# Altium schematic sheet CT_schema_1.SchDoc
size 532 x 318 mm
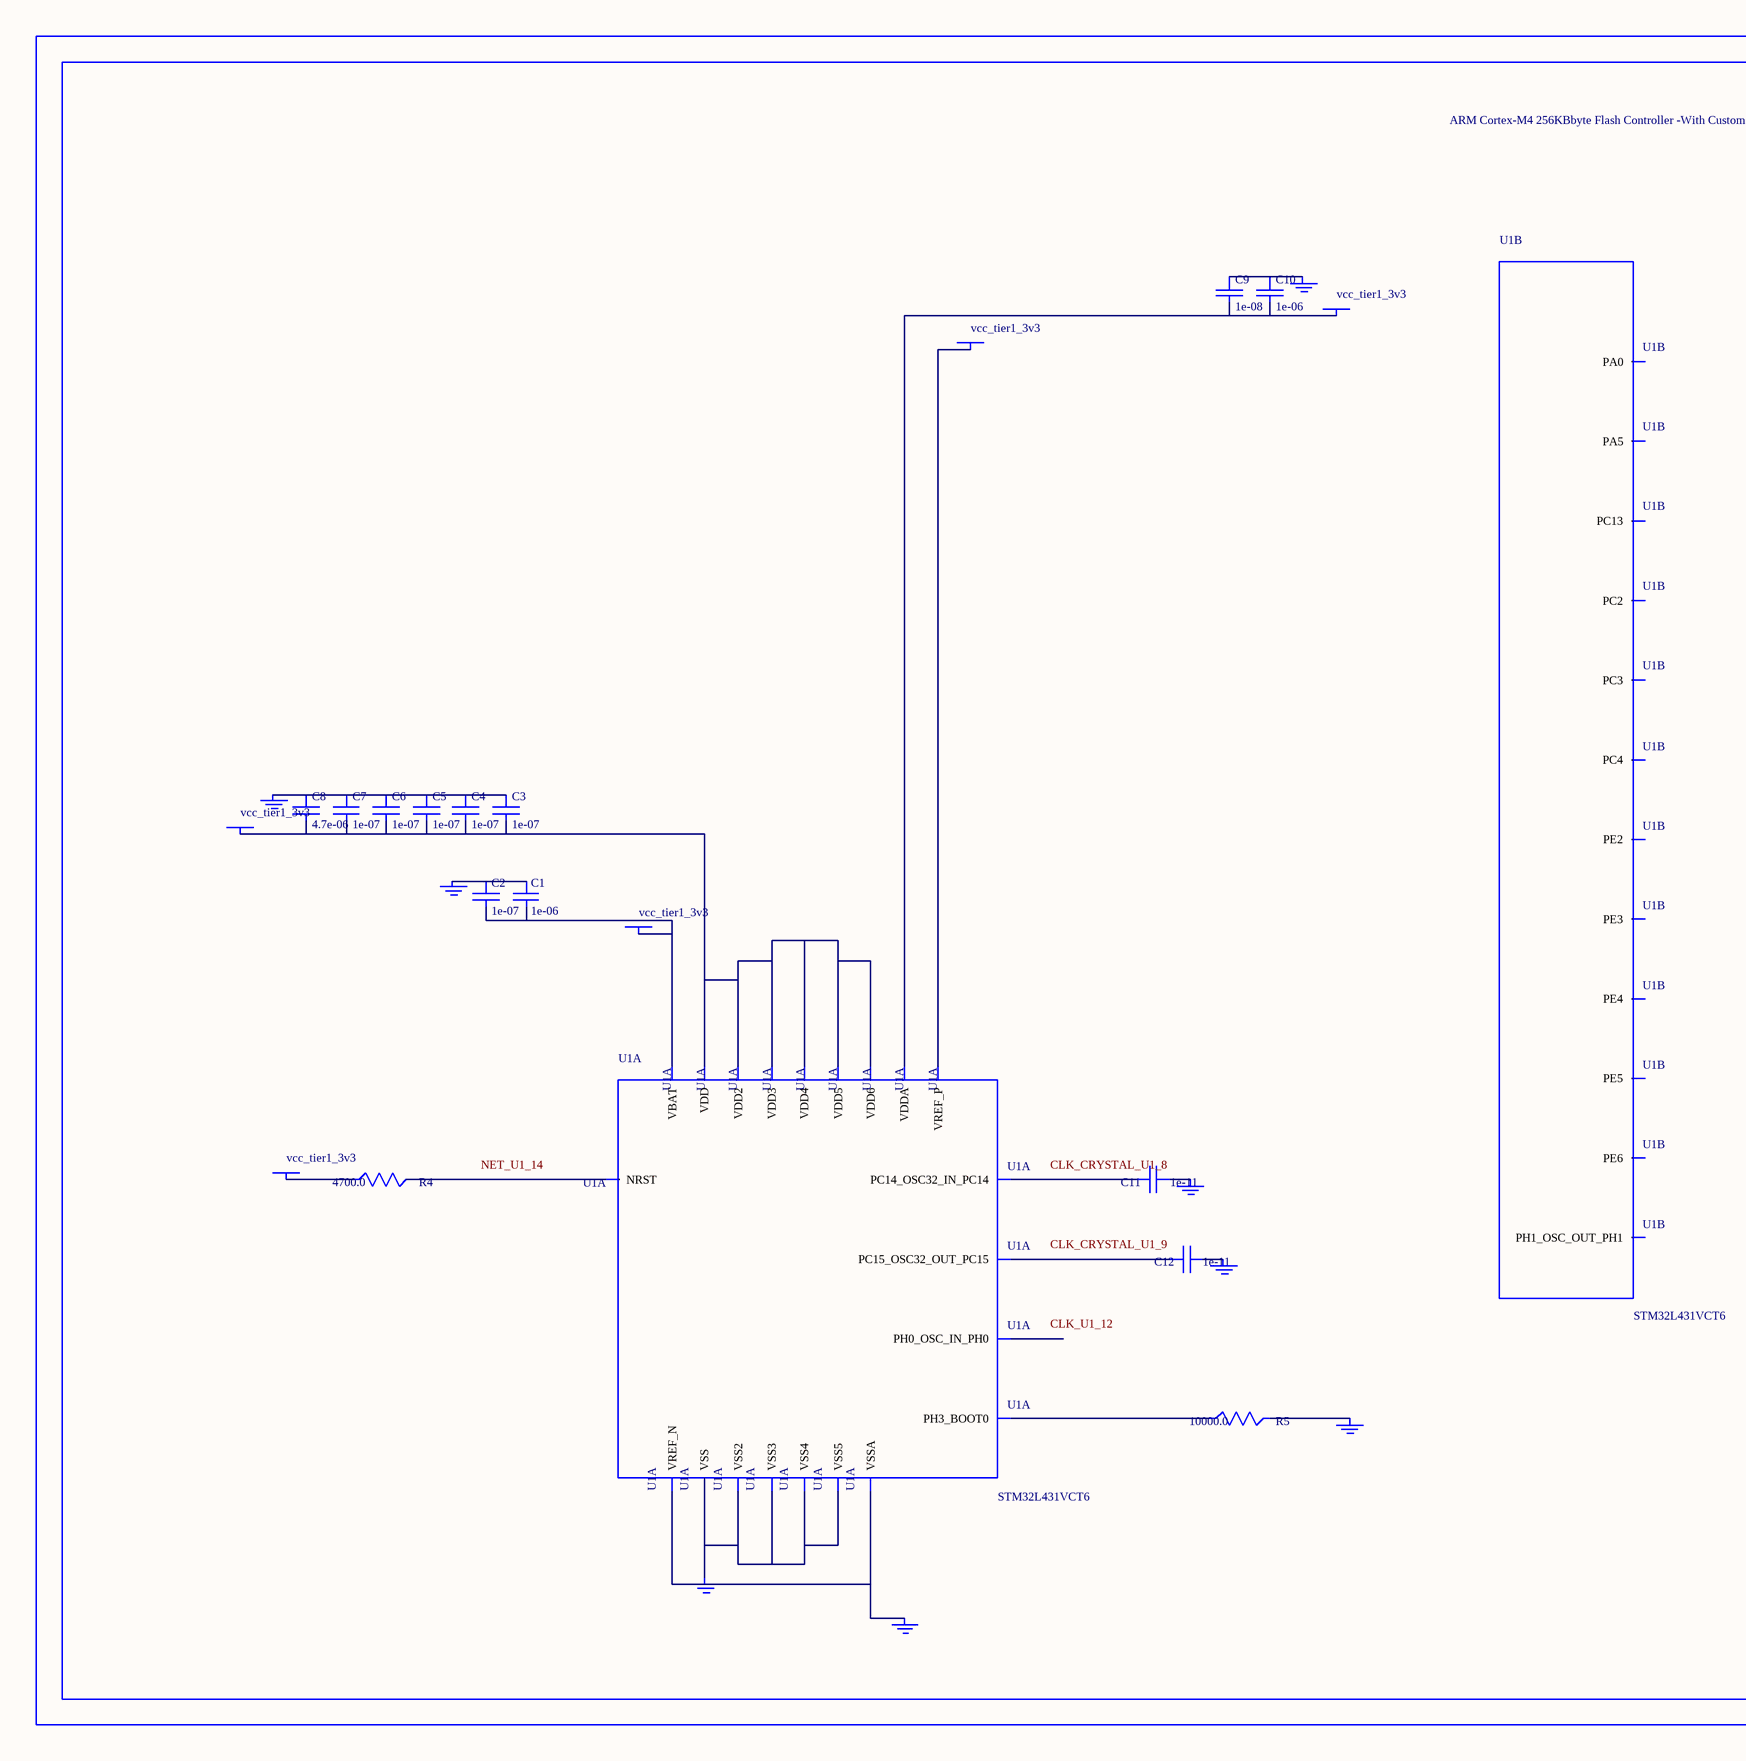
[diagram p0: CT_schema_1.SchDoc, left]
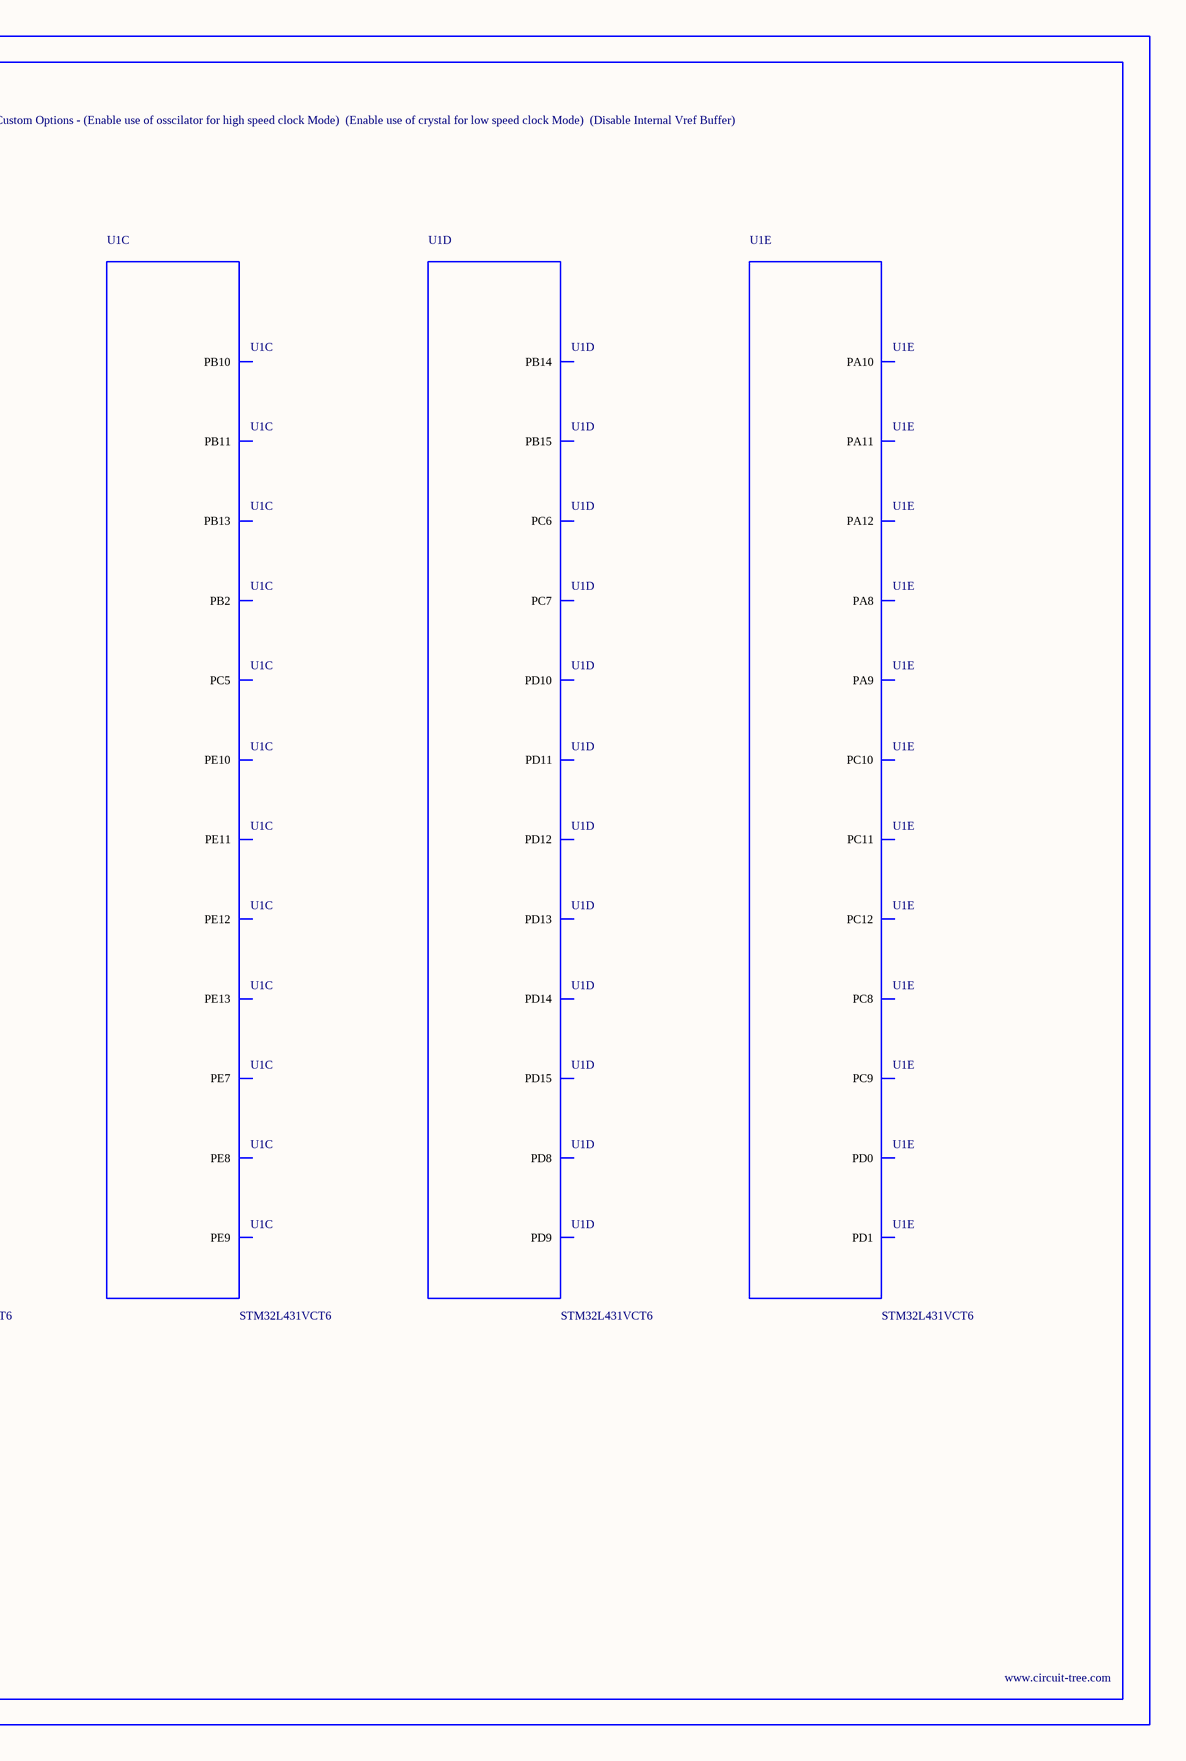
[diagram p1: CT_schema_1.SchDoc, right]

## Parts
BORDER0  (no value)
C1  1e-06  [C0603]
C2  1e-07  [C0603]
C3  1e-07  [C0603]
C4  1e-07  [C0603]
C5  1e-07  [C0603]
C6  1e-07  [C0603]
C7  1e-07  [C0603]
C8  4.7e-06  [C0603]
C9  1e-08  [C0603]
C10  1e-06  [C0603]
C11  1e-11  [C0402]
C12  1e-11  [C0402]
GND_INSTANCE_0_0  (no value)
GND_INSTANCE_0_1  (no value)
GND_INSTANCE_0_2  (no value)
GND_INSTANCE_0_3  (no value)
GND_INSTANCE_0_4  (no value)
GND_INSTANCE_0_5  (no value)
GND_INSTANCE_0_6  (no value)
GND_INSTANCE_0_7  (no value)
POWER_INSTANCE_0_0  vcc_tier1_3v3
POWER_INSTANCE_0_1  vcc_tier1_3v3
POWER_INSTANCE_0_2  vcc_tier1_3v3
POWER_INSTANCE_0_3  vcc_tier1_3v3
POWER_INSTANCE_0_4  vcc_tier1_3v3
R4  4700.0  [R0603]
R5  10000.0  [R0603]
U1  STM32L431VCT6  [LQFP100]  (parts A,B,C,D,E of 8)

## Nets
NetC1_1: C1.1 C2.1 GND_INSTANCE_0_0.0(GND)
NetC1_2: C1.2 C2.2 POWER_INSTANCE_0_0.0(PWR) U1.6(VBAT)
NetC3_1: C3.1 C4.1 C5.1 C6.1 C7.1 C8.1 GND_INSTANCE_0_3.0(GND)
NetC3_2: C3.2 C4.2 C5.2 C6.2 C7.2 C8.2 POWER_INSTANCE_0_1.0(PWR) U1.11(VDD) U1.28(VDD2) U1.50(VDD3) U1.73(VDD4) U1.75(VDD5) U1.100(VDD6)
NetC9_1: C9.1 C10.1 GND_INSTANCE_0_5.0(GND)
NetC9_2: C9.2 C10.2 POWER_INSTANCE_0_3.0(PWR) U1.22(VDDA)
NetC11_1: C11.1 GND_INSTANCE_0_1.0(GND)
NetC11_2: C11.2 U1.8(PC14_OSC32_IN_PC14)
NetC12_1: C12.1 GND_INSTANCE_0_2.0(GND)
NetC12_2: C12.2 U1.9(PC15_OSC32_OUT_PC15)
NetGND_INSTANCE_0_4_0: GND_INSTANCE_0_4.0(GND) U1.19(VSSA) U1.20(VREF_N)
NetGND_INSTANCE_0_6_0: GND_INSTANCE_0_6.0(GND) R5.2
NetGND_INSTANCE_0_7_0: GND_INSTANCE_0_7.0(GND) U1.10(VSS) U1.27(VSS2) U1.49(VSS3) U1.74(VSS4) U1.99(VSS5)
NetPOWER_INSTANCE_0_2_0: POWER_INSTANCE_0_2.0(PWR) U1.21(VREF_P)
NetPOWER_INSTANCE_0_4_0: POWER_INSTANCE_0_4.0(PWR) R4.1
NetR4_2: R4.2 U1.14(NRST)
NetR5_1: R5.1 U1.94(PH3_BOOT0)

Not connected (* = marked no-connect by the designer): U1 1(PE2) 2(PE3) 3(PE4) 4(PE5) 5(PE6) 7(PC13) 12(PH0_OSC_IN_PH0) 13(PH1_OSC_OUT_PH1) 17(PC2) 18(PC3) 23(PA0) 30(PA5) 33(PC4) 34(PC5) 37(PB2) 38(PE7) 39(PE8) 40(PE9) 41(PE10) 42(PE11) 43(PE12) 44(PE13) 47(PB10) 48(PB11) 52(PB13) 53(PB14) 54(PB15) 55(PD8) 56(PD9) 57(PD10) 58(PD11) 59(PD12) 60(PD13) 61(PD14) 62(PD15) 63(PC6) 64(PC7) 65(PC8) 66(PC9) 67(PA8) 68(PA9) 69(PA10) 70(PA11) 71(PA12) 78(PC10) 79(PC11) 80(PC12) 81(PD0) 82(PD1)

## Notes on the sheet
- Labels drawn without touching a wire or pin: CLK_CRYSTAL_U1_8, CLK_CRYSTAL_U1_9, CLK_U1_12, NET_U1_14

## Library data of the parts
BORDER0 = BORDER_PAGE0
C1 C10 = C0603C105K3RACTU
C2-C7 = 06035C104K4Z2A
C8 = GRM188R6YA475KE15D
C9 = 06035C103K4Z2A
C11 C12 = C0402C100K3GACTU
GND_INSTANCE_0_0-GND_INSTANCE_0_7 = GND
POWER_INSTANCE_0_0-POWER_INSTANCE_0_4 = PWR
R4 = RC0603JR-074K7L
R5 = RC0603JR-0710KL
